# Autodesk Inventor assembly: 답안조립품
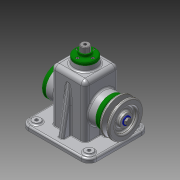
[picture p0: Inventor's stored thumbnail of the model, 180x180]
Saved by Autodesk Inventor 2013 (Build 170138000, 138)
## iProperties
Created: 2016-01
Part Number: 답안조립품
Document SubType Name: Assembly
Designer: User
Author: User
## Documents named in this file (19)
- C:\Users\User\Desktop\460126V1006\답안조립품.iam
- C:\Users\User\Desktop\460126V1006\본체.ipt
- C:\Users\User\Desktop\460126V1006\앞커버.ipt
- C:\Users\User\Desktop\460126V1006\뒤커버.ipt
- C:\Users\User\Desktop\460126V1006\오일실 15 25 7.ipt
- C:\Users\User\Desktop\460126V1006\베어링 15 x 35 x 11.ipt
- C:\Users\User\Desktop\460126V1006\멈춤링 15 x 1.ipt
- C:\Users\User\Desktop\460126V1006\편심축.ipt
- C:\Users\User\Desktop\460126V1006\상부부시.ipt
- C:\Users\User\Desktop\460126V1006\링크.ipt
- C:\Users\User\Desktop\460126V1006\슬라이드바.ipt
- C:\Users\User\Desktop\460126V1006\고정핀.ipt
- C:\Users\User\Desktop\460126V1006\멈춤링 6 x 5.ipt
- C:\Users\User\Desktop\460126V1006\V-벨트풀리.ipt
- C:\Users\User\Desktop\460126V1006\키 5 x 5 x 14.ipt
- C:\Users\User\Desktop\460126V1006\볼트 M6 x 12.ipt
- C:\Users\User\Desktop\460126V1006\볼트 M4 x 10.ipt
- C:\Users\User\Desktop\460126V1006\볼트 M3 x 8.ipt
- C:\Users\User\Desktop\460126V1006\와셔.ipt
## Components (15 placed, 5 different names)
1. 고정핀:1 — 플러쉬:2
2. V-벨트풀리:1
3. ISO 4018 M6 x 12:1 — 각도:1
4. ISO 4762 M4 x 10:1
5. ISO 4762 M4 x 10:2
6. ISO 4762 M4 x 10:3
7. ISO 4762 M4 x 10:4
8. ISO 4762 M4 x 10:5
9. ISO 4762 M4 x 10:6
10. ISO 4762 M4 x 10:7
11. ISO 4762 M4 x 10:8
12. ISO 4762 M3 x 8:1
13. ISO 4762 M3 x 8:2
14. ISO 4762 M3 x 8:3
15. ISO 4762 M3 x 8:4
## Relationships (2: Flush 1, Angle 1)
- 플러쉬:2 [Flush]: 고정핀:1
- 각도:1 [Angle]: ISO 4018 M6 x 12:1
